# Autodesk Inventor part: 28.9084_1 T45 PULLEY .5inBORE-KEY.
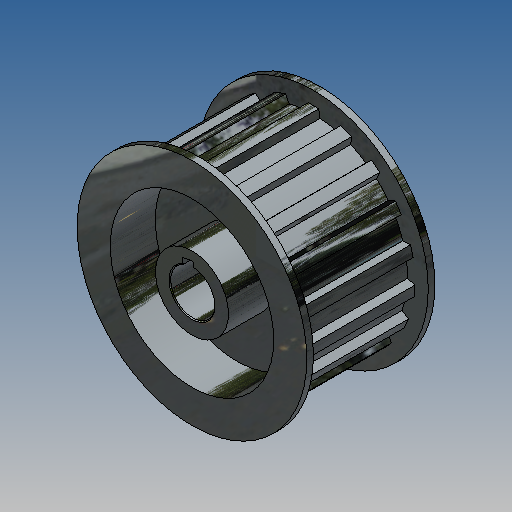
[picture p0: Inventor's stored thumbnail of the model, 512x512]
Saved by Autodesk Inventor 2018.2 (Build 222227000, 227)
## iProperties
Created: 2006-12
Document SubType Name: Modeling
Designer: Andy Moles
Material: Aluminum-6061
Part Number: 28.9084_1 T45 PULLEY .5inBORE-KEY.
Density: 2.71 g/cm^3
Mass: 151.298 g
Surface Area: 238.799 cm^2
Volume: 55.8293 cm^3
Appearance: Zinc
Author: Andy Moles
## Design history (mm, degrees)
sketch "Sketch1"
  geometry: L1 (-1.927, 26.982)-(-1.524, 29.17); L2 (1.927, 26.982)-(1.524, 29.17); L3 (11.073, 27.03)-(10.707, 24.842); L4 (15.084, 22.455)-(16.683, 23.977); L5 (19.077, 22.12)-(18.136, 20.071); L6 (21.534, 16.371)-(23.587, 17.23); L7 (25.254, 14.678)-(23.643, 13.144); L8 (25.717, 8.391)-(27.944, 8.508); L9 (28.652, 5.683)-(26.63, 4.755); L10 (27.049, -0.307)-(29.196, -0.889); L11 (28.945, -3.928)-(26.741, -4.085); L12 (25.484, -9.074)-(27.339, -10.286); L13 (26.084, -13.147)-(23.954, -12.569); L14 (21.157, -16.857)-(22.493, -18.635); L15 (20.429, -20.878)-(18.546, -19.693); L16 (14.537, -22.813)-(15.224, -24.929); L17 (12.543, -26.38)-(11.147, -24.648); L18 (6.342, -26.297)-(6.304, -28.522); L19 (3.298, -29.023)-(2.54, -26.931); L20 (-2.54, -26.931)-(-3.298, -29.023); L21 (-6.304, -28.522)-(-6.342, -26.297); L22 (-11.183, -24.631)-(-12.509, -26.396); L23 (-15.224, -24.929)-(-14.537, -22.813); L24 (-18.546, -19.693)-(-20.429, -20.878); L25 (-22.494, -18.635)-(-21.157, -16.856); L26 (-23.935, -12.604)-(-26.101, -13.113); L27 (-27.325, -10.322)-(-25.484, -9.074); L28 (-26.731, -4.15)-(-28.945, -3.928); L29 (-29.196, -0.89)-(-27.049, -0.307); L30 (-26.63, 4.756)-(-28.652, 5.685); L31 (-27.892, 8.674)-(-25.696, 8.455); L32 (-23.643, 13.144)-(-25.254, 14.679); L33 (-23.587, 17.23)-(-21.534, 16.371); L34 (-18.094, 20.109)-(-19.119, 22.083); L35 (-16.714, 23.955)-(-15.052, 22.477); L36 (-10.707, 24.842)-(-11.073, 27.03); L37 (-8.03, 28.085)-(-6.938, 26.146); L38 (6.938, 26.146)-(7.851, 28.135); A1 r 29.21 centre (0, 0) between (-16.714, 23.955) and (-19.119, 22.083); A2 r 27.051 centre (0, 0) between (-10.707, 24.842) and (-15.052, 22.477); A3 r 29.21 centre (0, 0) between (-8.03, 28.085) and (-11.073, 27.03); A4 r 27.051 centre (0, 0) between (-1.927, 26.982) and (-6.938, 26.146); A5 r 29.21 centre (0, 0) between (1.524, 29.17) and (-1.524, 29.17); A6 r 29.21 centre (0, 0) between (11.073, 27.03) and (7.851, 28.135); A7 r 29.21 centre (0, 0) between (19.077, 22.12) and (16.683, 23.977); A8 r 27.051 centre (0, 0) between (15.084, 22.455) and (10.707, 24.842); A9 r 27.051 centre (0, 0) between (21.534, 16.371) and (18.136, 20.071); A10 r 29.21 centre (0, 0) between (25.254, 14.678) and (23.587, 17.23); A11 r 27.051 centre (0, 0) between (25.717, 8.391) and (23.643, 13.144); A12 r 29.21 centre (0, 0) between (28.652, 5.683) and (27.944, 8.508); A13 r 27.051 centre (0, 0) between (27.049, -0.307) and (26.63, 4.755); A14 r 29.21 centre (0, 0) between (28.945, -3.928) and (29.196, -0.889); A15 r 27.051 centre (0, 0) between (25.484, -9.074) and (26.741, -4.085); A16 r 29.21 centre (0, 0) between (26.084, -13.147) and (27.339, -10.286); A17 r 27.051 centre (0, 0) between (21.157, -16.857) and (23.954, -12.569); A18 r 29.21 centre (0, 0) between (20.429, -20.878) and (22.493, -18.635); A19 r 27.051 centre (0, 0) between (14.537, -22.813) and (18.546, -19.693); A20 r 29.21 centre (0, 0) between (12.543, -26.38) and (15.224, -24.929); A21 r 27.051 centre (0, 0) between (6.342, -26.297) and (11.147, -24.648); A22 r 29.21 centre (0, 0) between (3.298, -29.023) and (6.304, -28.522); A23 r 27.051 centre (0, 0) between (-2.54, -26.931) and (2.54, -26.931); A24 r 29.21 centre (0, 0) between (-6.304, -28.522) and (-3.298, -29.023); A25 r 29.21 centre (0, 0) between (-15.224, -24.929) and (-12.509, -26.396); A26 r 29.21 centre (0, 0) between (-22.494, -18.635) and (-20.429, -20.878); A27 r 27.051 centre (0, 0) between (-11.183, -24.631) and (-6.342, -26.297); A28 r 27.051 centre (0, 0) between (-18.546, -19.693) and (-14.537, -22.813); A29 r 29.21 centre (0, 0) between (-27.325, -10.322) and (-26.101, -13.113); A30 r 27.051 centre (0, 0) between (-23.935, -12.604) and (-21.157, -16.856); A31 r 27.051 centre (0, 0) between (-26.731, -4.15) and (-25.484, -9.074); A32 r 29.21 centre (0, 0) between (-29.196, -0.89) and (-28.945, -3.928); A33 r 27.051 centre (0, 0) between (-26.63, 4.756) and (-27.049, -0.307); A34 r 29.21 centre (0, 0) between (-23.587, 17.23) and (-25.254, 14.679); A35 r 29.21 centre (0, 0) between (-27.892, 8.674) and (-28.652, 5.685); A36 r 27.051 centre (0, 0) between (-18.094, 20.109) and (-21.534, 16.371); A37 r 27.051 centre (0, 0) between (-23.643, 13.144) and (-25.696, 8.455); A38 r 27.051 centre (0, 0) between (6.938, 26.146) and (1.927, 26.982); 2 further points
  constraints: 77 point on circle, 76 end point, 38 centre point, 4 parallel, 2 coincident, 2 perpendicular
extrude "Extrusion1" new body sketch "Sketch1" stored distance "d19" = 33.02; taper "d20" = 0 deg
sketch "Sketch4"
  geometry: C1 r 33.02 at (0, 0); A1 r 27.051 centre (0, 0) between (6.938, 26.146) and (1.927, 26.982) reference
  constraints: 1 centre point, 1 coincident
  dimensions: "d24" = 66.04 diameter of C1
extrude "Extrusion3" join sketch "Sketch4" distance "d25" = 1.905; taper "d26" = 0 deg
sketch "Sketch5"
  geometry: C1 r 33.02 at (0, 0) reference; C2 r 10.5 at (0, 0); C3 r 23.5 at (0, 0)
  constraints: 2 centre point, 2 coincident
  dimensions: "d27" = 21 diameter of C2; "d28" = 47 diameter of C3
extrude "Extrusion4" cut sketch "Sketch5" distance "d29" = 12.954; taper "d30" = 0 deg
mirror "Mirror1"
sketch "Sketch6"
  geometry: C1 r 10.5 at (0, 0) reference; C2 r 4 at (0, 0)
  constraints: 1 centre point, 1 coincident
  dimensions: "d31" = 8 diameter of C2
extrude "Extrusion5" cut sketch "Sketch6" extent not by distance; stored distance "d32" = 12.954; taper "d33" = 0 deg
sketch "Sketch7"
  geometry: L1 (0, 0)-(-4.457, 26.71); L2 (-8.03, 28.085)-(-6.938, 26.146) reference; L3 (-1.927, 26.982)-(-1.524, 29.17) reference; L4 (-2.578, 5.803)-(-2.862, 7.505); L5 (-2.862, 7.505)-(0.27, 8.028); L6 (0.27, 8.028)-(0.554, 6.326); C1 r 4 at (0, 0) reference; C2 r 10.5 at (0, 0) reference; A1 r 6.35 centre (0, 0) between (-2.578, 5.803) and (0.554, 6.326); 1 further point
  constraints: 8 end point, 2 parallel, 2 point on circle, 1 centre point, 1 coincident, 1 midpoint, 1 perpendicular, 1 point on line
  dimensions: "d34" = 12.7 diameter of A1; "d35" = 19.92 deg angle of L2 L1; "d36" = 19.9212 deg angle of L1 L3 (derived); "d38" = 3.175 distance of L4.end L5.end; "d39" = 14.224 dimension on A1 L5
extrude "Extrusion6" cut sketch "Sketch7" extent not by distance; stored distance "d40" = 10; taper "d41" = 0 deg
chamfer "Chamfer1" distance "d42" = 0.25; stored, may be unused: second distance "d43" = 2, angle "d44" = 45 deg
body "Solid1"
other parameters: "d1" = 2.159
